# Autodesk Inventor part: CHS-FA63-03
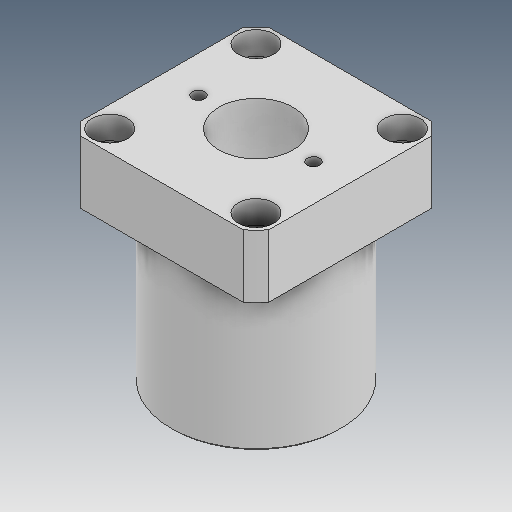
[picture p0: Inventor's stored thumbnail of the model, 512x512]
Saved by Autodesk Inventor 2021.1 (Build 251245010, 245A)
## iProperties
Created: 2019-05
Part Number: CHS-FA63-03
Material: Ogólny
Document SubType Name: Modeling
Designer: user
Density: 1 g/cm^3
Appearance: Domyślna
Author: user
Revision Number: ÈÎºÎ
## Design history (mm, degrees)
feature "ÊäÈë1"
node "Bryła1"
